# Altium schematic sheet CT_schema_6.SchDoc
size 372 x 245 mm
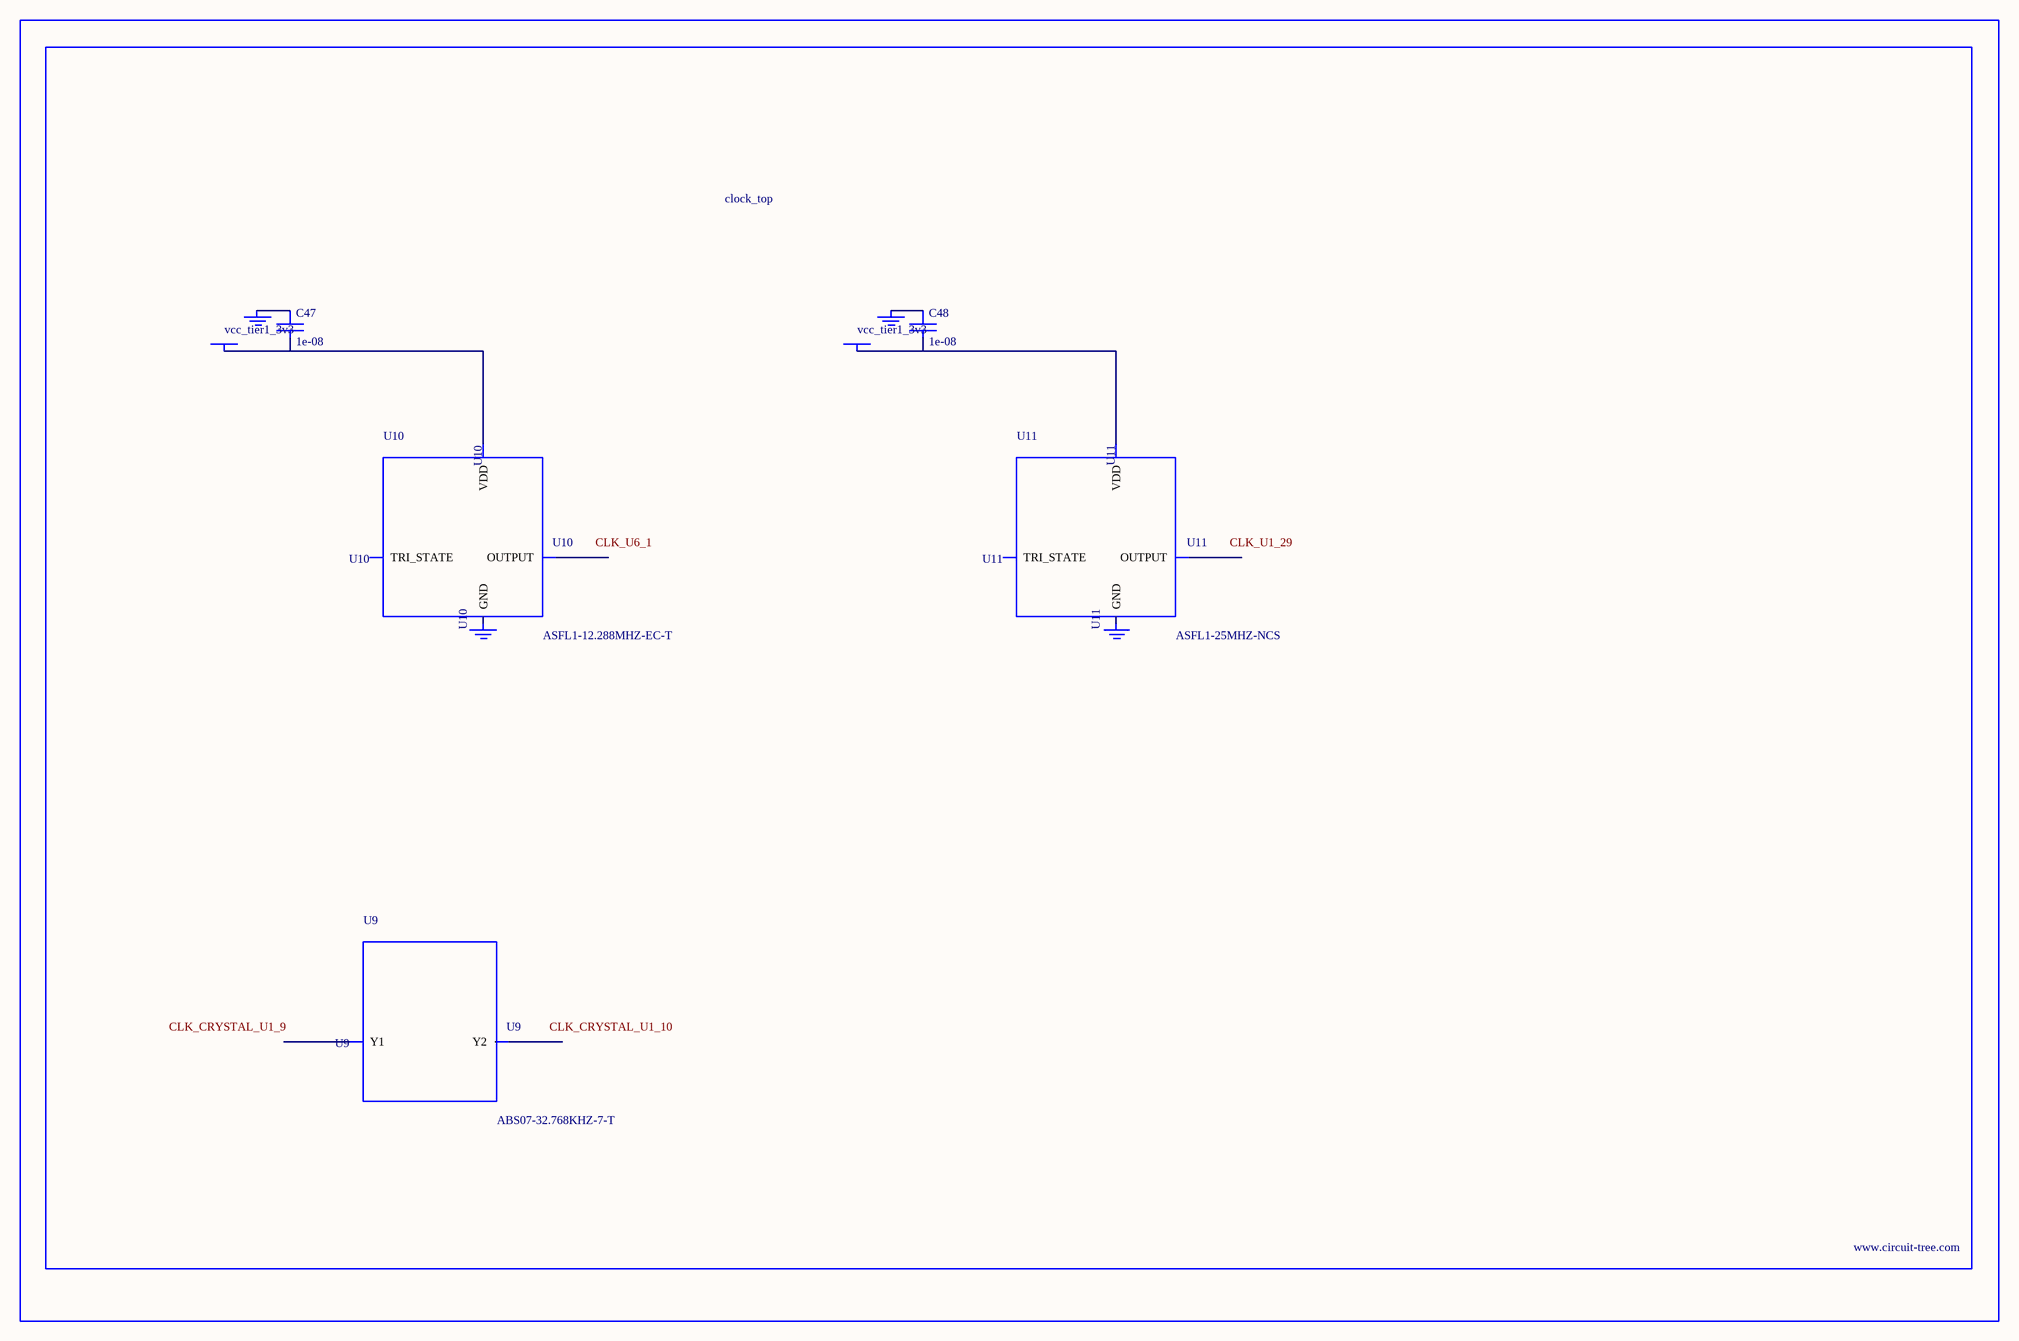
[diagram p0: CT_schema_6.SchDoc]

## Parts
BORDER5  (no value)
C47  1e-08  [C0402]
C48  1e-08  [C0402]
GND_INSTANCE_5_0  (no value)
GND_INSTANCE_5_1  (no value)
GND_INSTANCE_5_2  (no value)
GND_INSTANCE_5_3  (no value)
POWER_INSTANCE_5_0  vcc_tier1_3v3
POWER_INSTANCE_5_1  vcc_tier1_3v3
U9  ABS07-32.768KHZ-7-T  [ABS07-32.768KHZ-7-T]
U10  ASFL1-12.288MHZ-EC-T  [ASFL1]
U11  ASFL1-25MHZ-NCS  [ASFL1]

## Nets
NetC47_1: C47.1 GND_INSTANCE_5_0.0(GND)
NetC47_2: C47.2 POWER_INSTANCE_5_0.0(PWR) U10.4(VDD)
NetC48_1: C48.1 GND_INSTANCE_5_2.0(GND)
NetC48_2: C48.2 POWER_INSTANCE_5_1.0(PWR) U11.4(VDD)

Not connected (* = marked no-connect by the designer): GND_INSTANCE_5_1 0(GND); GND_INSTANCE_5_3 0(GND); U9 1(Y1) 2(Y2); U10 1(TRI_STATE) 2(GND) 3(OUTPUT); U11 1(TRI_STATE) 2(GND) 3(OUTPUT)

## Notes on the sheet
- Labels drawn without touching a wire or pin: CLK_CRYSTAL_U1_9, CLK_CRYSTAL_U1_10, CLK_U1_29, CLK_U6_1

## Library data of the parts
BORDER5 = BORDER_PAGE5
C47 C48 = C0402C103K3RAC
GND_INSTANCE_5_0-GND_INSTANCE_5_3 = GND
POWER_INSTANCE_5_0 POWER_INSTANCE_5_1 = PWR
